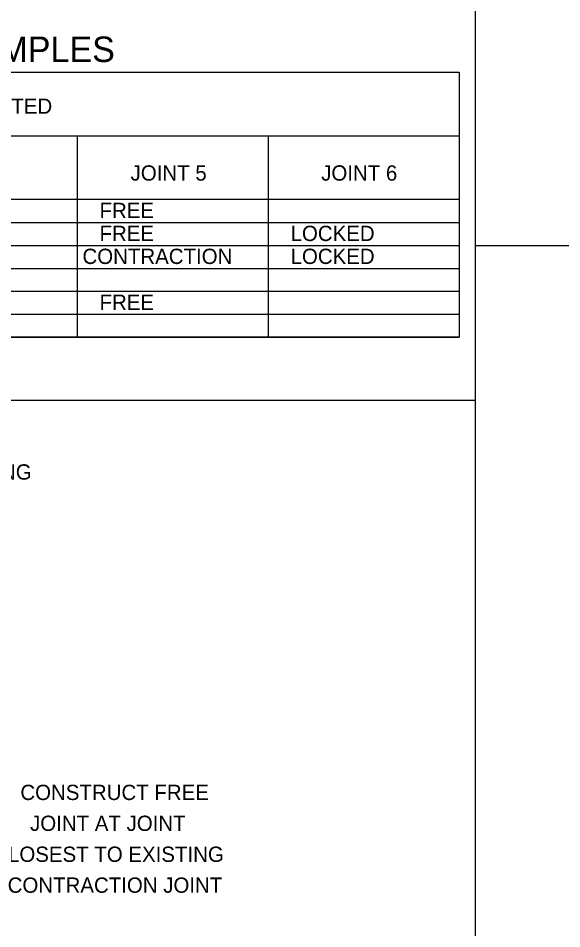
# Model space of a CAD drawing. Extents: x 1375738 to 1375905, y 380661 to 380875.
# Drawn here: x 1375840.42 to 1375857.49, y 380818.43 to 380847.01 of the extents above; entities that cross this region are included whole.
import ezdxf

# ---------------------------------------------------------------- set-up
doc = ezdxf.new("R2010")
doc.units = 0
doc.layers.add('R_Border', color=7, linetype='Continuous')
doc.layers.add('R_Draft', color=7, linetype='Continuous')

msp = doc.modelspace()

# ---------------------------------------------------------------- linework, layer by layer
at = {"layer": 'R_Border'}
for p, q in [((1375854.78, 380770.053), (1375854.78, 380872.783)), ((1375854.78, 380839.872), (1375902.509, 380839.872)), ((1375786.095, 380835.027), (1375854.78, 380835.027))]:
    msp.add_line(p, q, dxfattribs=at)
at = {"layer": 'R_Draft'}
for p, q in [((1375810.272, 380845.32), (1375854.272, 380845.32)), ((1375854.272, 380845.318), (1375854.272, 380841.32)), ((1375818.272, 380843.319), (1375854.272, 380843.319)), ((1375842.272, 380843.319), (1375842.272, 380841.32)), ((1375848.272, 380843.319), (1375848.272, 380841.32)), ((1375842.272, 380841.32), (1375836.272, 380841.32)), ((1375848.272, 380841.32), (1375842.272, 380841.32)), ((1375842.272, 380841.32), (1375842.272, 380840.6)), ((1375854.272, 380841.32), (1375848.272, 380841.32)), ((1375848.272, 380841.32), (1375848.272, 380840.6)), ((1375854.272, 380841.32), (1375854.272, 380840.6)), ((1375836.272, 380840.6), (1375842.272, 380840.6)), ((1375842.272, 380840.6), (1375842.272, 380839.88)), ((1375842.272, 380840.6), (1375848.272, 380840.6)), ((1375848.272, 380840.6), (1375854.272, 380840.6)), ((1375848.272, 380840.6), (1375848.272, 380839.88)), ((1375854.272, 380840.6), (1375854.272, 380839.88)), ((1375836.272, 380839.88), (1375842.272, 380839.88)), ((1375842.272, 380839.88), (1375842.272, 380839.16)), ((1375842.272, 380839.88), (1375848.272, 380839.88)), ((1375848.272, 380839.88), (1375854.272, 380839.88)), ((1375848.272, 380839.88), (1375848.272, 380839.16)), ((1375854.272, 380839.88), (1375854.272, 380839.16)), ((1375836.272, 380839.16), (1375842.272, 380839.16)), ((1375842.272, 380839.16), (1375842.272, 380838.44)), ((1375842.272, 380839.16), (1375848.272, 380839.16)), ((1375848.272, 380839.16), (1375854.272, 380839.16)), ((1375848.272, 380839.16), (1375848.272, 380838.44)), ((1375854.272, 380839.16), (1375854.272, 380838.44)), ((1375836.272, 380838.44), (1375842.272, 380838.44)), ((1375842.272, 380838.44), (1375848.272, 380838.44)), ((1375842.272, 380838.44), (1375842.272, 380837.72)), ((1375848.272, 380838.44), (1375854.272, 380838.44)), ((1375848.272, 380838.44), (1375848.272, 380837.72)), ((1375854.272, 380838.44), (1375854.272, 380837.72)), ((1375836.272, 380837.72), (1375842.272, 380837.72)), ((1375842.272, 380837.72), (1375842.272, 380837)), ((1375842.272, 380837.72), (1375848.272, 380837.72)), ((1375848.272, 380837.72), (1375854.272, 380837.72)), ((1375848.272, 380837.72), (1375848.272, 380837)), ((1375854.272, 380837.72), (1375854.272, 380837)), ((1375854.272, 380837), (1375810.272, 380837)), ((1375836.272, 380837), (1375842.272, 380837)), ((1375842.272, 380837), (1375848.272, 380837)), ((1375848.272, 380837), (1375854.272, 380837))]:
    msp.add_line(p, q, dxfattribs=at)

# ---------------------------------------------------------------- texts
for s, height, p in [('TYPICAL SLAB REPLACEMENT EXAMPLES', 0.7996, (1375821.587, 380845.636)), ('TYPE OF JOINT TO BE CONSTRUCTED', 0.48, (1375829.505, 380844.01)), ('JOINT 5', 0.48, (1375843.949, 380841.913)), ('JOINT 6', 0.48, (1375849.934, 380841.913)), ('   FREE    ', 0.48, (1375842.438, 380840.737)), ('   FREE    ', 0.48, (1375842.438, 380840.017)), ('   LOCKED  ', 0.48, (1375848.438, 380840.017)), ('CONTRACTION', 0.48, (1375842.438, 380839.297)), ('   LOCKED  ', 0.48, (1375848.438, 380839.297)), ('   FREE    ', 0.48, (1375842.438, 380837.857)), ('WARPING', 0.48, (1375837.776, 380832.529)), ('CONSTRUCT FREE', 0.48, (1375840.488, 380822.473)), ('JOINT AT JOINT', 0.48, (1375840.792, 380821.503)), ('CLOSEST TO EXISTING', 0.48, (1375839.636, 380820.532)), ('CONTRACTION JOINT', 0.48, (1375840.089, 380819.562))]:
    msp.add_text(s, height=height, dxfattribs=at).set_placement(p)

doc.saveas('drawing.dxf')
